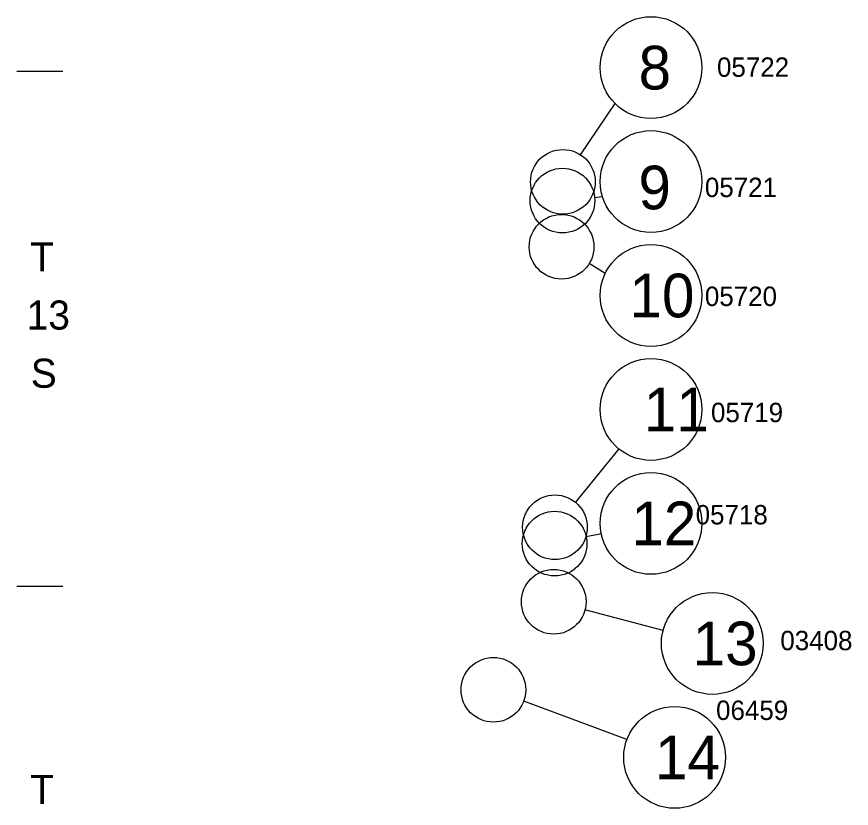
# Model space of a CAD drawing. Extents: x -17742 to 32032, y -17264 to 5867.
# Drawn here: x 27246 to 28967, y 2238 to 3871 of the extents above; entities that cross this region are included whole.
import ezdxf

# ---------------------------------------------------------------- set-up
doc = ezdxf.new("R2010")
doc.units = 0
for name, color, linetype in [('2', 7, 'Continuous'), ('Default', 7, 'Continuous'), ('R_Annotation', 7, 'Continuous'), ('R_No Plot', 7, 'Continuous')]:
    doc.layers.add(name, color=color, linetype=linetype)

msp = doc.modelspace()

# ---------------------------------------------------------------- linework, layer by layer
at = {"layer": 'Default'}
for p, q in [((27340.7, 3758.1), (27245.7, 3758.1)), ((27340.7, 2696.1), (27245.7, 2696.1))]:
    msp.add_line(p, q, dxfattribs=at)
at = {"layer": 'R_Annotation'}
for p, q in [((28479.6, 3691.9), (28407.5, 3586)), ((28452.9, 3499.7), (28438.1, 3497.8)), ((28459.3, 3341.7), (28426.3, 3361.8)), ((28487.5, 2979.8), (28397.9, 2869.8)), ((28451.7, 2804.7), (28420.4, 2798.1)), ((28578.8, 2605.1), (28417.6, 2647.5)), ((28504.2, 2380.2), (28291.3, 2459.6))]:
    msp.add_line(p, q, dxfattribs=at)
for centre, radius in [((28553.9, 3766.1), 105), ((28553.9, 3531.1), 105), ((28372.1, 3530.5), 66.7), ((28371.3, 3491.8), 66.7), ((28369.4, 3396.6), 66.7), ((28553.9, 3296.1), 105), ((28553.9, 3061.1), 105), ((28553.9, 2826.1), 105), ((28355.7, 2818.1), 66.7), ((28355.1, 2784.4), 66.7), ((28353.3, 2664.4), 66.7), ((28680.3, 2578.5), 105), ((28228.9, 2482.9), 66.7), ((28602.6, 2343.5), 105)]:
    msp.add_circle(centre, radius, dxfattribs=at)

# ---------------------------------------------------------------- texts
at = {"layer": '2'}
for s, p in [('T', (27273.6, 3345.8)), ('13', (27266.3, 3225.8)), ('S', (27274.8, 3105.8)), ('T', (27273.6, 2247.3))]:
    msp.add_text(s, height=60, dxfattribs=at).set_placement(p)
at = {"layer": 'R_Annotation'}
for s, p in [('8', (28528.3, 3721.1)), ('9', (28528, 3473.9)), ('10', (28509.6, 3251.1)), ('11', (28539, 3016.1)), ('12', (28513.5, 2781.1)), ('13', (28639.9, 2533.5)), ('14', (28562.2, 2298.5))]:
    msp.add_text(s, height=90, dxfattribs=at).set_placement(p)
at = {"layer": 'R_No Plot'}
for s, p in [('05722', (28690, 3747.1)), ('05721', (28665, 3499.1)), ('05720', (28665, 3274.4)), ('05719', (28677.6, 3034.9)), ('05718', (28646, 2824)), ('03408', (28820.6, 2564.5)), ('06459', (28688.1, 2420.7))]:
    msp.add_text(s, height=40, dxfattribs=at).set_placement(p)

doc.saveas('drawing.dxf')
